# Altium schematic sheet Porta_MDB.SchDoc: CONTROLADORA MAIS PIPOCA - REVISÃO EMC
size A3; DocumentNumber: GA0078; SheetNumber: 14; SheetTotal: 17
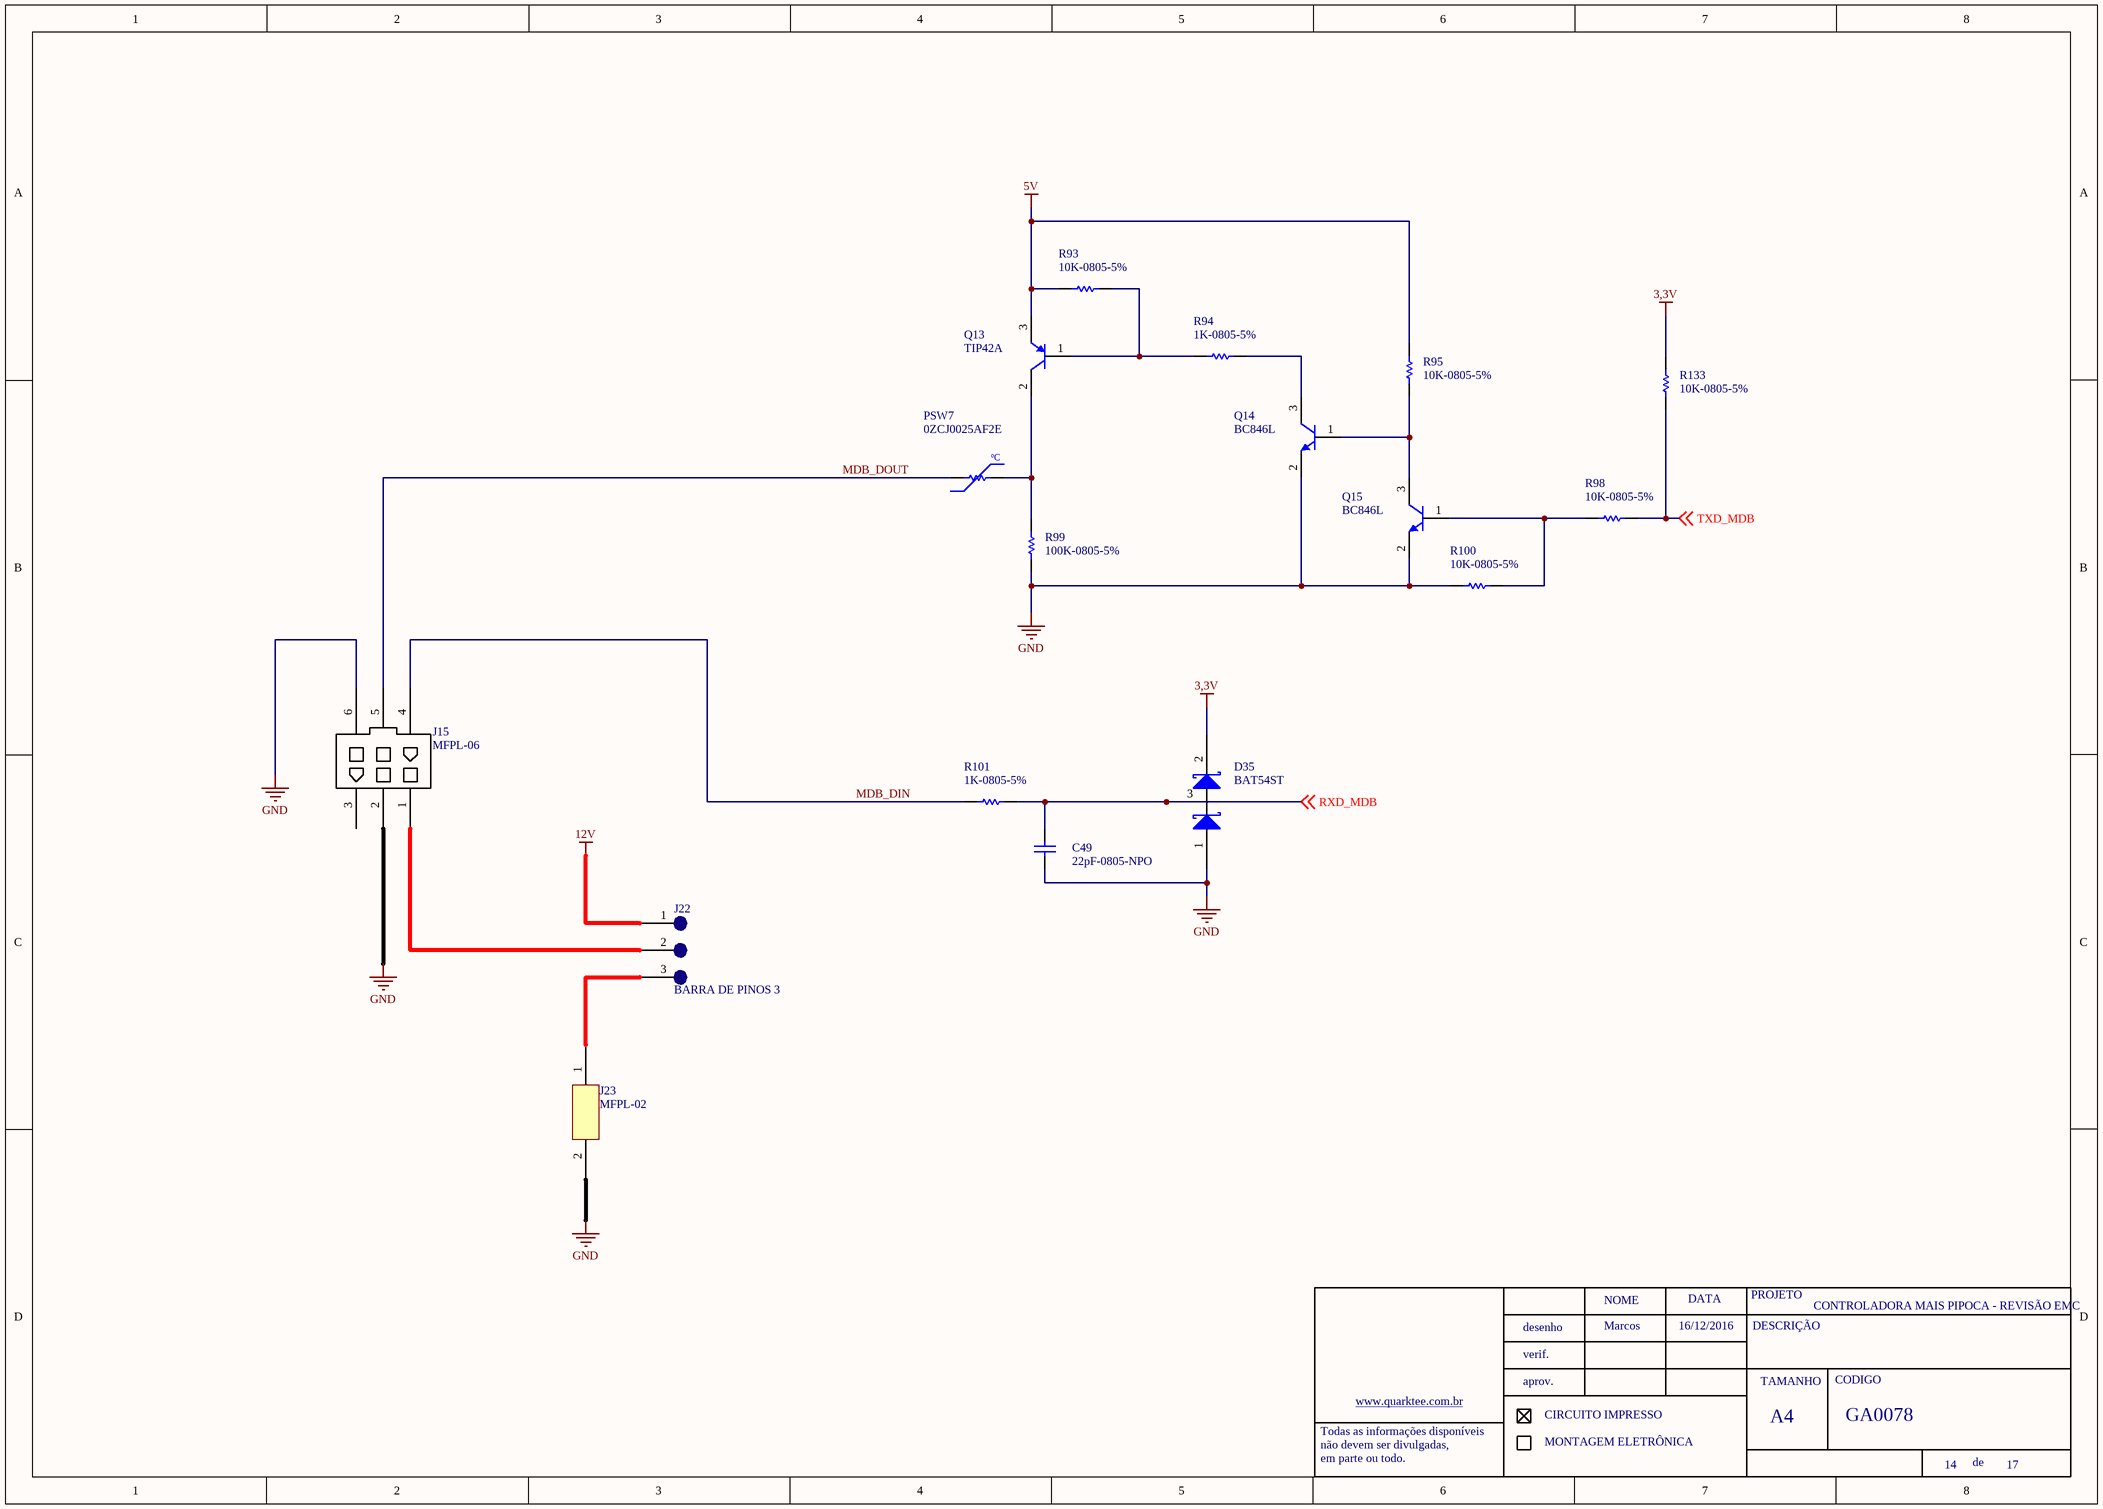
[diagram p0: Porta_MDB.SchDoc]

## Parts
C49  22pF-0805-NPO  [0805-REVISADO ONDA]
D35  BAT54ST  [SOT23 - REVISADO ONDA]
J15  MFPL-06
J22  BARRA DE PINOS 3
J23  MFPL-02
PSW7  0ZCJ0025AF2E  [1206-REVISADO ONDA]
Q13  TIP42A  [DPAK REVISADO ONDA]
Q14  BC846L  [SOT23 - REVISADO ONDA]
Q15  BC846L  [SOT23 - REVISADO ONDA]
R93  10K-0805-5%  [0805-REVISADO ONDA]
R94  1K-0805-5%  [0805-REVISADO ONDA]
R95  10K-0805-5%  [0805-REVISADO ONDA]
R98  10K-0805-5%  [0805-REVISADO ONDA]
R99  100K-0805-5%  [0805-REVISADO ONDA]
R100  10K-0805-5%  [0805-REVISADO ONDA]
R101  1K-0805-5%  [0805-REVISADO ONDA]
R133  10K-0805-5%  [0805-REVISADO ONDA]

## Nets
3,3V: D35.2 R133.2
5V: Q13.3(E) R93.1 R95.2
12V: J22.1
GND: C49.1 D35.1 J15.2 J15.6 J23.2 Q14.2(E) Q15.2(E) R99.1 R100.1
MDB_DIN: J15.4 R101.1
MDB_DOUT: J15.5 PSW7.1
RXD_MDB: C49.2 D35.3 R101.2 ; off-sheet RXD_MDB
TXD_MDB: R98.2 R133.1 ; off-sheet TXD_MDB
NetJ15_1: J15.1 J22.2
NetJ22_3: J22.3 J23.1
NetPSW7_2: PSW7.2 Q13.2(C) R99.2
NetQ13_1: Q13.1(B) R93.2 R94.1
NetQ14_1: Q14.1(B) Q15.3(C) R95.1
NetQ14_3: Q14.3(C) R94.2
NetQ15_1: Q15.1(B) R98.1 R100.2

Not connected (* = marked no-connect by the designer): J15 3

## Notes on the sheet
- Marcos
- 16/12/2016

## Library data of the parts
J22 = JUMPER 3
PSW7 = PTC 2A-120V
Q14 Q15 = BC846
